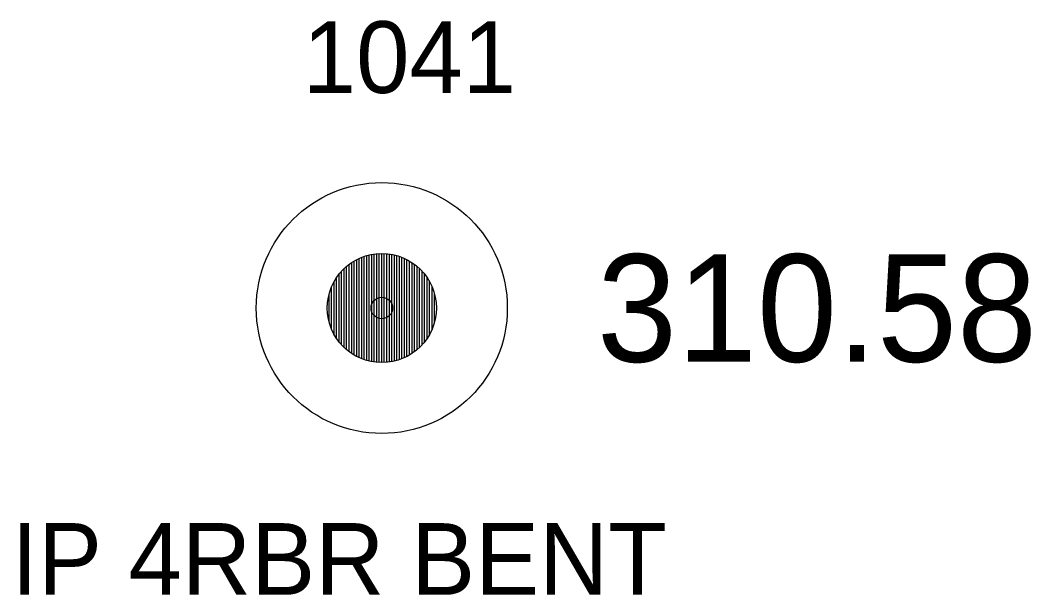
# Model space of a CAD drawing. Extents: x 1865045 to 1867370, y 910391 to 914218.
# Drawn here: x 1866244.98 to 1866259.07, y 913381.25 to 913389.27 of the extents above; entities that cross this region are included whole.
import ezdxf

# ---------------------------------------------------------------- set-up
doc = ezdxf.new("R2010")
doc.units = 0
for name, color, linetype in [('RD_EX_DV_Prop_txCode', 7, 'Continuous'), ('RD_EX_DV_PropPin', 7, 'Continuous'), ('RD_EX_TX_DV_Prop_ELEV', 7, 'Continuous'), ('RD_SMD_Locator', 7, 'Continuous')]:
    doc.layers.add(name, color=color, linetype=linetype)

msp = doc.modelspace()

# ---------------------------------------------------------------- linework, layer by layer
at = {"layer": 'RD_EX_DV_PropPin'}
for p, q in [((1866249.676, 913384.575), (1866249.676, 913385.927)), ((1866249.711, 913384.558), (1866249.711, 913385.944)), ((1866249.746, 913384.543), (1866249.746, 913385.959)), ((1866249.781, 913384.531), (1866249.781, 913385.971)), ((1866249.816, 913384.52), (1866249.816, 913385.982)), ((1866249.851, 913384.51), (1866249.851, 913385.992)), ((1866249.886, 913384.503), (1866249.886, 913385.999)), ((1866249.921, 913384.497), (1866249.921, 913386.005)), ((1866249.956, 913384.493), (1866249.956, 913386.009)), ((1866249.991, 913384.491), (1866249.991, 913386.011)), ((1866250.026, 913384.49), (1866250.026, 913386.012)), ((1866250.061, 913384.491), (1866250.061, 913386.011)), ((1866250.096, 913384.493), (1866250.096, 913386.009)), ((1866250.131, 913384.497), (1866250.131, 913386.005)), ((1866250.166, 913384.503), (1866250.166, 913385.999)), ((1866250.201, 913384.51), (1866250.201, 913385.992)), ((1866250.236, 913384.52), (1866250.236, 913385.982)), ((1866250.271, 913384.531), (1866250.271, 913385.971)), ((1866250.306, 913384.543), (1866250.306, 913385.959)), ((1866250.342, 913384.558), (1866250.342, 913385.944)), ((1866250.377, 913384.575), (1866250.377, 913385.927)), ((1866249.501, 913384.7), (1866249.501, 913385.802)), ((1866249.536, 913384.669), (1866249.536, 913385.833)), ((1866249.571, 913384.641), (1866249.571, 913385.861)), ((1866249.606, 913384.616), (1866249.606, 913385.886)), ((1866249.641, 913384.595), (1866249.641, 913385.907)), ((1866250.412, 913384.595), (1866250.412, 913385.907)), ((1866250.447, 913384.616), (1866250.447, 913385.886)), ((1866250.482, 913384.641), (1866250.482, 913385.861)), ((1866250.517, 913384.669), (1866250.517, 913385.833)), ((1866250.552, 913384.7), (1866250.552, 913385.802)), ((1866249.396, 913384.824), (1866249.396, 913385.678)), ((1866249.431, 913384.777), (1866249.431, 913385.725)), ((1866249.466, 913384.736), (1866249.466, 913385.766)), ((1866250.587, 913384.736), (1866250.587, 913385.766)), ((1866250.622, 913384.777), (1866250.622, 913385.725)), ((1866250.657, 913384.824), (1866250.657, 913385.678)), ((1866249.326, 913384.953), (1866249.326, 913385.549)), ((1866249.361, 913384.881), (1866249.361, 913385.621)), ((1866250.692, 913384.881), (1866250.692, 913385.621)), ((1866250.727, 913384.953), (1866250.727, 913385.549)), ((1866249.291, 913385.055), (1866249.291, 913385.447)), ((1866250.762, 913385.055), (1866250.762, 913385.447))]:
    msp.add_line(p, q, dxfattribs=at)
for radius in [1.75, 0.761]:
    msp.add_circle((1866250.026, 913385.251), radius, dxfattribs=at)
at = {"layer": 'RD_SMD_Locator'}
msp.add_circle((1866250.026, 913385.251), 0.15, dxfattribs=at)

# ---------------------------------------------------------------- texts
at = {"layer": 'RD_EX_DV_Prop_txCode'}
for s, p in [('1041', (1866248.924, 913388.251)), ('IP 4RBR BENT', (1866244.861, 913381.251))]:
    msp.add_text(s, height=1, dxfattribs=at).set_placement(p)
at = {"layer": 'RD_EX_TX_DV_Prop_ELEV'}
msp.add_text('310.58', height=1.5, dxfattribs=at).set_placement((1866253.026, 913384.501))

doc.saveas('drawing.dxf')
